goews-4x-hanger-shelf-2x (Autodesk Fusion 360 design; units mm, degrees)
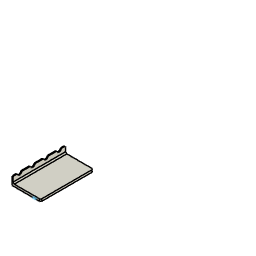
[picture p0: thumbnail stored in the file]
base_feature "Base Feature2"
base_feature "Base Feature1" bodies "Quad Plate Blank"
delete_face "DeleteFace1"
split "Split1" bodies "Quad Plate Blank (1)"
delete_face "DeleteFace2"
move_face "MoveFace1"
fillet "Fillet1" radius 3.75
combine "Combine1" bodies "Quad Plate Blank"
chamfer "Chamfer1" distance 4
move_face "MoveFace2"
extrude "Extrude1" cut sketch "Reconstructed-Sketch2" blind -1060
named bodies: "Quad Plate Blank", "Quad Plate Blank (1)"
